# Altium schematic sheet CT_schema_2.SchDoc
size 283 x 135 mm
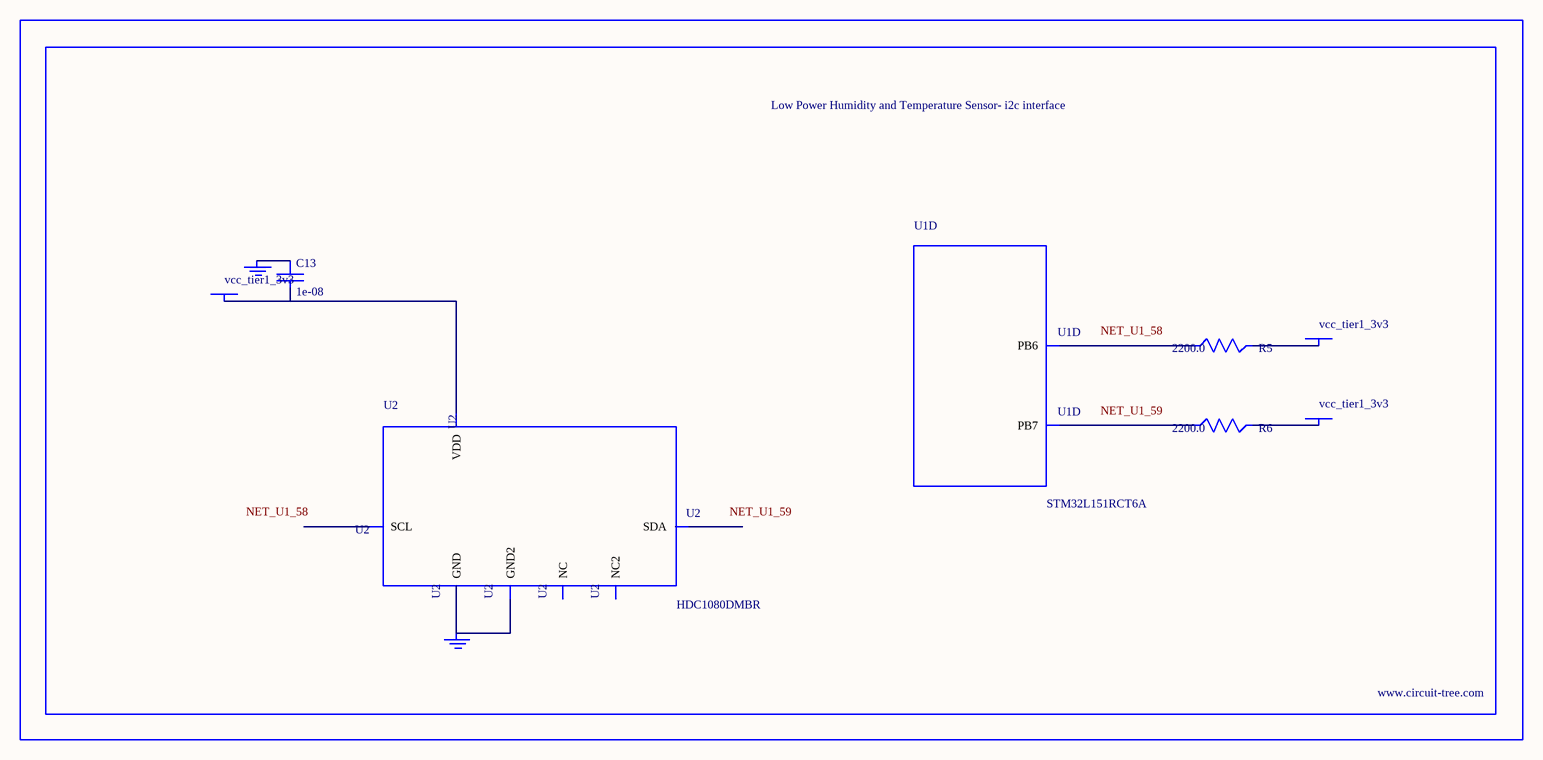
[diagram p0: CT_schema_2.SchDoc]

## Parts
BORDER1  (no value)
C13  1e-08  [C0402]
GND_INSTANCE_1_0  (no value)
GND_INSTANCE_1_1  (no value)
POWER_INSTANCE_1_0  vcc_tier1_3v3
POWER_INSTANCE_1_1  vcc_tier1_3v3
POWER_INSTANCE_1_2  vcc_tier1_3v3
R5  2200.0  [R0603]
R6  2200.0  [R0603]
U1  STM32L151RCT6A  [LQFP64]  (part D of 8)
U2  HDC1080DMBR  [WSON-6]

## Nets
NetC13_1: C13.1 GND_INSTANCE_1_0.0(GND)
NetC13_2: C13.2 POWER_INSTANCE_1_0.0(PWR) U2.5(VDD)
NetGND_INSTANCE_1_1_0: GND_INSTANCE_1_1.0(GND) U2.2(GND) U2.PAD(GND2)
NetPOWER_INSTANCE_1_1_0: POWER_INSTANCE_1_1.0(PWR) R5.2
NetPOWER_INSTANCE_1_2_0: POWER_INSTANCE_1_2.0(PWR) R6.2
NetR5_1: R5.1 U1.58(PB6)
NetR6_1: R6.1 U1.59(PB7)

Not connected (* = marked no-connect by the designer): U2 1(SDA) 3(NC) 4(NC2) 6(SCL)

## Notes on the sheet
- Labels drawn without touching a wire or pin: NET_U1_58, NET_U1_59

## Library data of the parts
BORDER1 = BORDER_PAGE1
C13 = C0402C103K3RAC
GND_INSTANCE_1_0 GND_INSTANCE_1_1 = GND
POWER_INSTANCE_1_0-POWER_INSTANCE_1_2 = PWR
R5 R6 = RC0603JR-072K2L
